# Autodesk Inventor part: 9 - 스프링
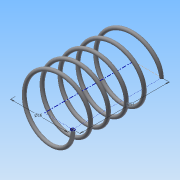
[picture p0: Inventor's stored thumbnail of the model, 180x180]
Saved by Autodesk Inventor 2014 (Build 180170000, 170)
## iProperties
Created: 2015-06
Part Number: 9 - 스프링
Material: 강철, 연강
Document SubType Name: Modeling
Designer: Administrator
Density: 7.86 g/cm^3
Appearance: 강철
Mass: 1.5292 g
Surface Area: 7.8715 cm^2
Volume: 0.194555 cm^3
Author: Administrator
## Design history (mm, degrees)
sketch "스케치1"
  geometry: L1 (0, 0)-(8, 0); L2 (8, 0)-(8, 14.5); L3 (8, 14.5)-(0, 14.5); L4 (0, 14.5)-(0, 0); C1 r 0.5 at (8, 0)
  constraints: 8 end point, 2 parallel, 1 centre point, 1 coincident, 1 horizontal, 1 perpendicular
  dimensions: "d1" = 1 diameter of C1; "d2" = 16 diameter of L2 L4; "d3" = 14.5 distance of L1.end L2.end (derived)
feature "코일1" sketch "스케치1" pitch "d4" = 10; turns "d6" = 5; dims "d5" = 14.5 (= d3), "d7" = 0, angle "d8" = 90 deg, angle "d9" = 90 deg, "d10" = 0, "d11" = 0
sketch "스케치2"
  geometry: L1 (-8.5, 0)-(-7.5, 0) reference; 1 further point
  constraints: 1 horizontal alignment
extrude "돌출1" cut sketch "스케치2" stored distance "d12" = 10; taper "d13" = 0 deg
node "작업 평면1"
sketch "스케치3"
  geometry: L1 (8.5, 0)-(7.5, 0) reference; 1 further point
  constraints: 1 horizontal alignment
extrude "돌출2" cut sketch "스케치3" stored distance "d15" = 10; taper "d16" = 0 deg
node "솔리드1"
node "절단 모서리 투영1"
node "절단 모서리 투영2"
other parameters: "d14" = -14.5 (= -d3)
